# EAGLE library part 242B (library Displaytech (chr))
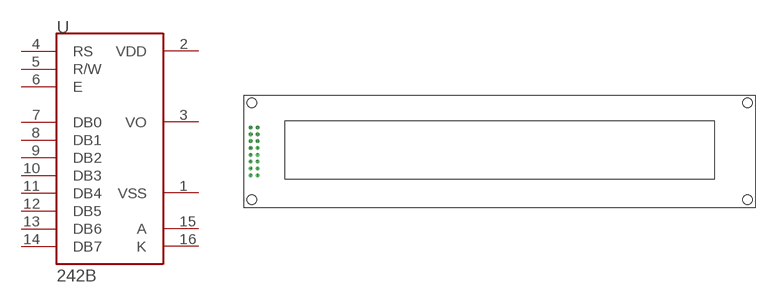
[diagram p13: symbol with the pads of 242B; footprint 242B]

Designator prefix -

## 242B  [242B]
1  VSS  pwr
2  VDD  pwr
3  VO  in
4  RS
5  R/W
6  E
7  DB0
8  DB1
9  DB2
10  DB3
11  DB4
12  DB5
13  DB6
14  DB7
15  A  pwr
16  K  pwr

## Footprint 242B (pad centres in mm)
drill 1.016 round: 1 0,0; 2 -2.54,0; 3 0,2.54; 4 -2.54,2.54; 5 0,5.08; 6 -2.54,5.08; 7 0,7.62; 8 -2.54,7.62; 9 0,10.16; 10 -2.54,10.16; 11 0,12.7; 12 -2.54,12.7; 13 0,15.24; 14 -2.54,15.24; 15 0,17.78; 16 -2.54,17.78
